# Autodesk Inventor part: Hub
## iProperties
Created: 2010-09
Part Number: Hub
Document SubType Name: Modeling
Designer: nguyenducthang
Density: 1 g/cm^3
Mass: 19.5725 g
Surface Area: 77.1229 cm^2
Volume: 19.5725 cm^3
Author: nguyenducthang
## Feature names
1. Revolution1
2. Extrusion3
3. Extrusion4
4. Revolution2
5. Circular Pattern1
6. Revolution3
7. Chamfer3
8. Extrusion5
9. Circular Pattern2
